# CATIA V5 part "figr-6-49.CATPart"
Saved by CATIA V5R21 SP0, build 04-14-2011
Part number: Part1
Bounding box of the stored display mesh (mm): x -54.76 to 54.76, y -32.885 to 32.885, z 0 to 59
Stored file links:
  D:\CATIA V5R21 E-RESOURCES\CATIA-V5R21\catia-v5r21-prt\c06-catia-v5r21-prt\c06-catia-v5r21-figr-6-49.CATPart
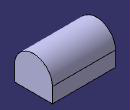
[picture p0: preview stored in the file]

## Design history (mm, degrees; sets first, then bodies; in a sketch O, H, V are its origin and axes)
Body1 (main body)
  Sketch1 on xy-plane, origin (0, 0, 0), H (1, 0, 0), V (0, 1, 0)
    line L1 (-54.7599, 32.8853) -> (54.7599, 32.8853)
    line L2 (54.7599, 32.8853) -> (54.7599, -32.8853)
    line L3 (54.7599, -32.8853) -> (-54.7599, -32.8853)
    line L4 (-54.7599, -32.8853) -> (-54.7599, 32.8853)
    axis line L5 (54.7599, -32.8853) -> (-54.7599, 32.8853)
    horizontal: L1 H, L3 H
    vertical: L2 V, L4 V
    midpoint: O L5
  Pad1: profile Sketch1, direction (0, 0, 1), length 59
  TritangentFillet1: Face1 face of Pad1, Face2 face of Pad1, RemoveFace face of Pad1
